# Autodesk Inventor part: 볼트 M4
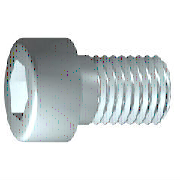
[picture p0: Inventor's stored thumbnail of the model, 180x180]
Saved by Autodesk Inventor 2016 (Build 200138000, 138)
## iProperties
IsCustomPart: 0
Created: 2014-10
Part Number: 볼트 M4
Material: 강철, 연강
Description: 6각머리 태핑 나사
Document SubType Name: Modeling
Standard: KS B 1003
Designer: KYOUNG IL JANG
Standards Organization: KS
Language: ko-KR
Size Designation: M 4 x 10
Categories: <MemberInstance><Categories><Category DisplayName="조임쇠" InternalName="e4da775c-781d-43d5-af7c-5136215cf5a6" Mnemonic="FSTN"><Category DisplayName="볼트" InternalN
Density: 7.86 g/cm^3
Mass: 2.0371 g
Surface Area: 3.0572 cm^2
Volume: 0.259174 cm^3
Appearance: 강철 - 광택
Author: SeoGD™ [www.esajin.kr]
Revision Number: 1
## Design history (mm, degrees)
sketch "스케치1"
  geometry: L1 (-1, 0)-(10, 0); L2 (10, 0)-(10, 2); L3 (10, 2)-(1.75, 2); L4 (1.75, 2)-(1.32, 2); L5 (1.32, 2)-(0, 2); L6 (0, 2)-(0, 3.5); L7 (0, 3.5)-(-4, 3.5); L8 (-4, 3.5)-(-4, 1.732); L9 (-4, 1.732)-(-2, 1.732); L10 (-2, 1.732)-(-1, 0); L11 (-6.8, 0)-(12.8, 0) reference; L12 (0, -0.7)-(0, 4.2) reference; L13 (1.75, 2)-(0, 2)
  constraints: 22 end point, 6 parallel, 2 collinear, 2 perpendicular, 1 horizontal, 1 point on line
  dimensions: "d1" = 8.25 distance from line of L3.end L2 (= GEL); "d2" = 0.42952 distance of L4.end L3.end (computed from GAL); "d3" = 4 distance between parallel lines of L8 L6 (= KOH); "d4" = 2 distance of L8.end L9.end (= INTI); "d5" = 60 deg angle of L10 L1; "d6" = 4 diameter of L3 L1 (= GD); "d7" = 4 diameter of L5 L1 (= BDM); "d8" = 3.4641 diameter of L9 L1 (= 1.1547 x SW); "d9" = 7 diameter of L7 L1 (= KOD); "d26" = 10 distance between parallel lines of L12 L2 (= NLG)
revolve "본체" sketch "스케치1" stored, may be unused: angle "d10" = 90 deg
sketch "스케치2"
  geometry: L1 (0, -4.9)-(0, 4.9) reference; L2 (-4.9, 0)-(4.9, 0) reference; L3 (1.732, 0)-(0.866, -1.5); L4 (0.866, -1.5)-(-0.866, -1.5); L5 (-0.866, -1.5)-(-1.732, 0); L6 (-1.732, 0)-(-0.866, 1.5); L7 (-0.866, 1.5)-(0.866, 1.5); L8 (0.866, 1.5)-(1.732, 0); 2 further points
  constraints: 12 end point, 1 coincident, 1 horizontal alignment, 1 point on line, 12 other
extrude "슬롯" join sketch "스케치2" stored distance "d11" = 10; taper "d12" = 0 deg
workplane "Work Plane1"
fillet "Fillet2" dims "d30" = 0.1 (= R)
body "Solid1"
fillet "모깎기1" dims "d17" = 0.4 (= RR)
feature "스레드" dims "d13" = 8.25 (= GEL), "d14" = 0
chamfer "모따기1" distance "d15" = 0.42941 (= -0.5 x SPD + 0.5 x GD); stored, may be unused: second distance "d16" = 0.42941 (= GUL), angle "d27" = 45 deg
other parameters: "GD" = 4 (= NND) [user parameter; used in 2 equation terms], "NLG" = 10 [user parameter; used in 1 equation term], "GEL" = 8.25 [user parameter; used in 2 equation terms], "KOD" = 7 [user parameter; used in 1 equation term], "KOH" = 4 [user parameter; used in 1 equation term], "INTI" = 2 [user parameter; used in 1 equation term], "GAL" = 0.42941 (= 0.61345 x PTC) [user parameter; used in 1 equation term], "GUL" = 0.42941 (= 0.61345 x PTC) [user parameter; used in 1 equation term], "BDM" = 4 (= NND) [user parameter; used in 1 equation term], "SW" = 3 [user parameter; used in 2 equation terms], "RR" = 0.4 [user parameter; used in 1 equation term], "SPD" = 3.14117 (= NND - 1.2269 x PTC) [user parameter; used in 1 equation term], "d19" = 0, "d28" = 0, "d29" = 0, "R" = 0.1 [user parameter; used in 1 equation term], "PHH" = 0.2 [user parameter], "GD1" = 3.14117 (= THREADDIA - 1.2269 x PTC) [user parameter], "THREADDIA" = 4 [user parameter; used in 1 equation term], "FAWI" = 45 deg [user parameter], "TPU" = 14.28571 (computed from PTC) [user parameter], "PTC" = 0.7 [user parameter; used in 5 equation terms], "NND" = 4 [user parameter; used in 3 equation terms], "TOA" = 30 deg [user parameter], "E0" = 3.465 (= 1.155 x SW) [user parameter]
